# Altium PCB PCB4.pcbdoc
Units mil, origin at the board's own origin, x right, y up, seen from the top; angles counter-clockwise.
Board outline 1996.06 x 3846.46 mil, 2 copper layers (Top Layer, Bottom Layer); 8 components, 12 nets, 57 pads, 0 vias.
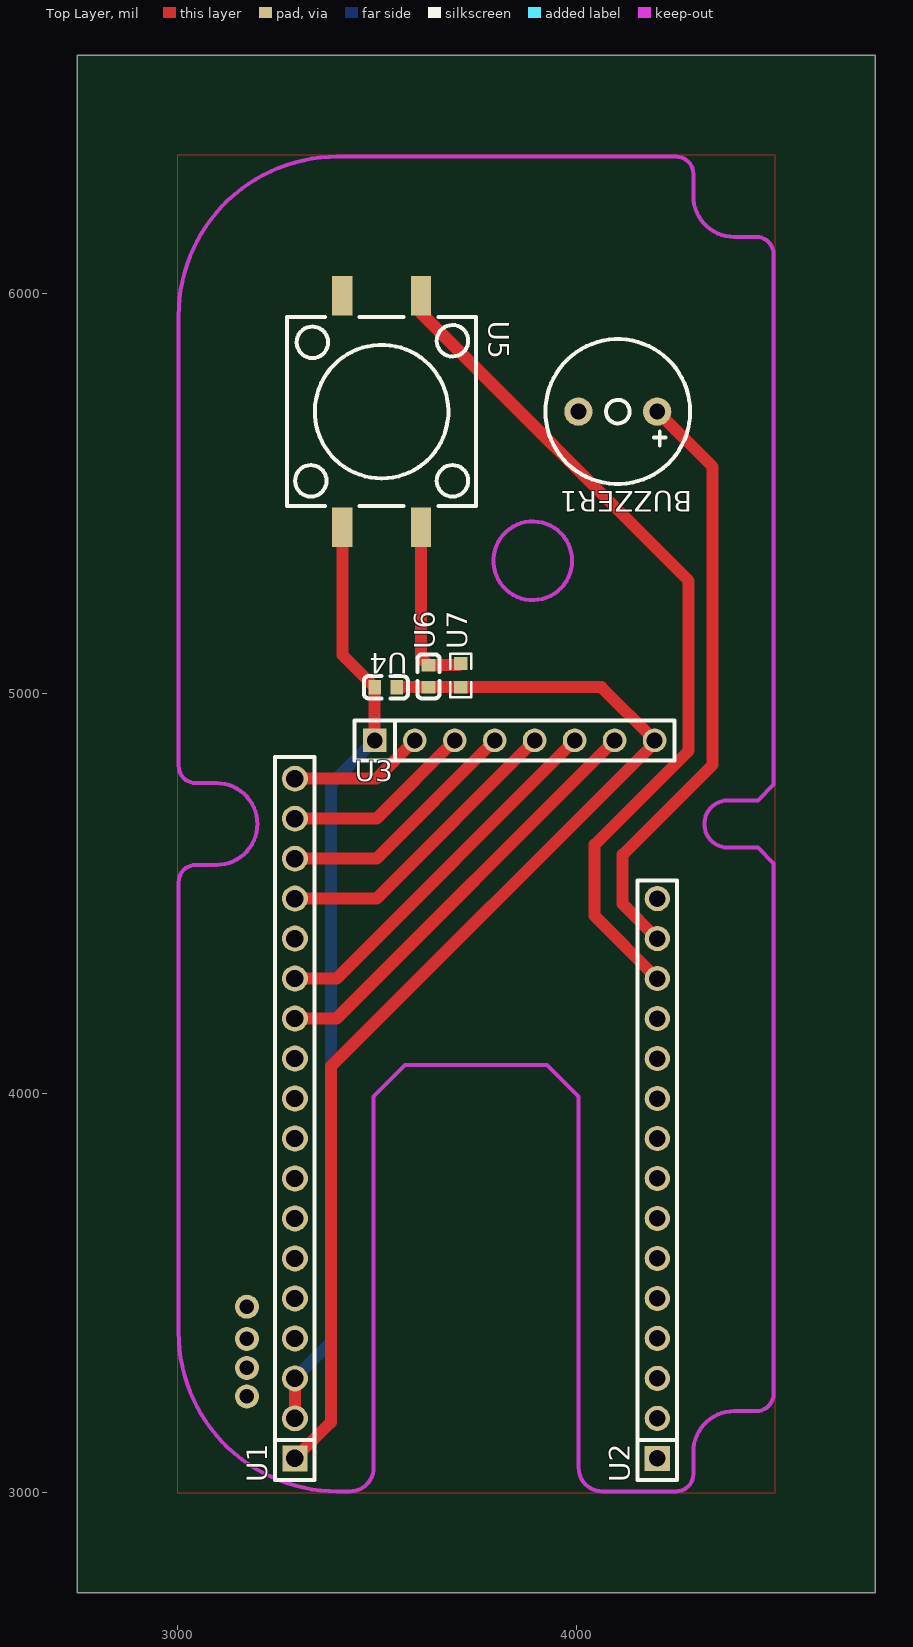
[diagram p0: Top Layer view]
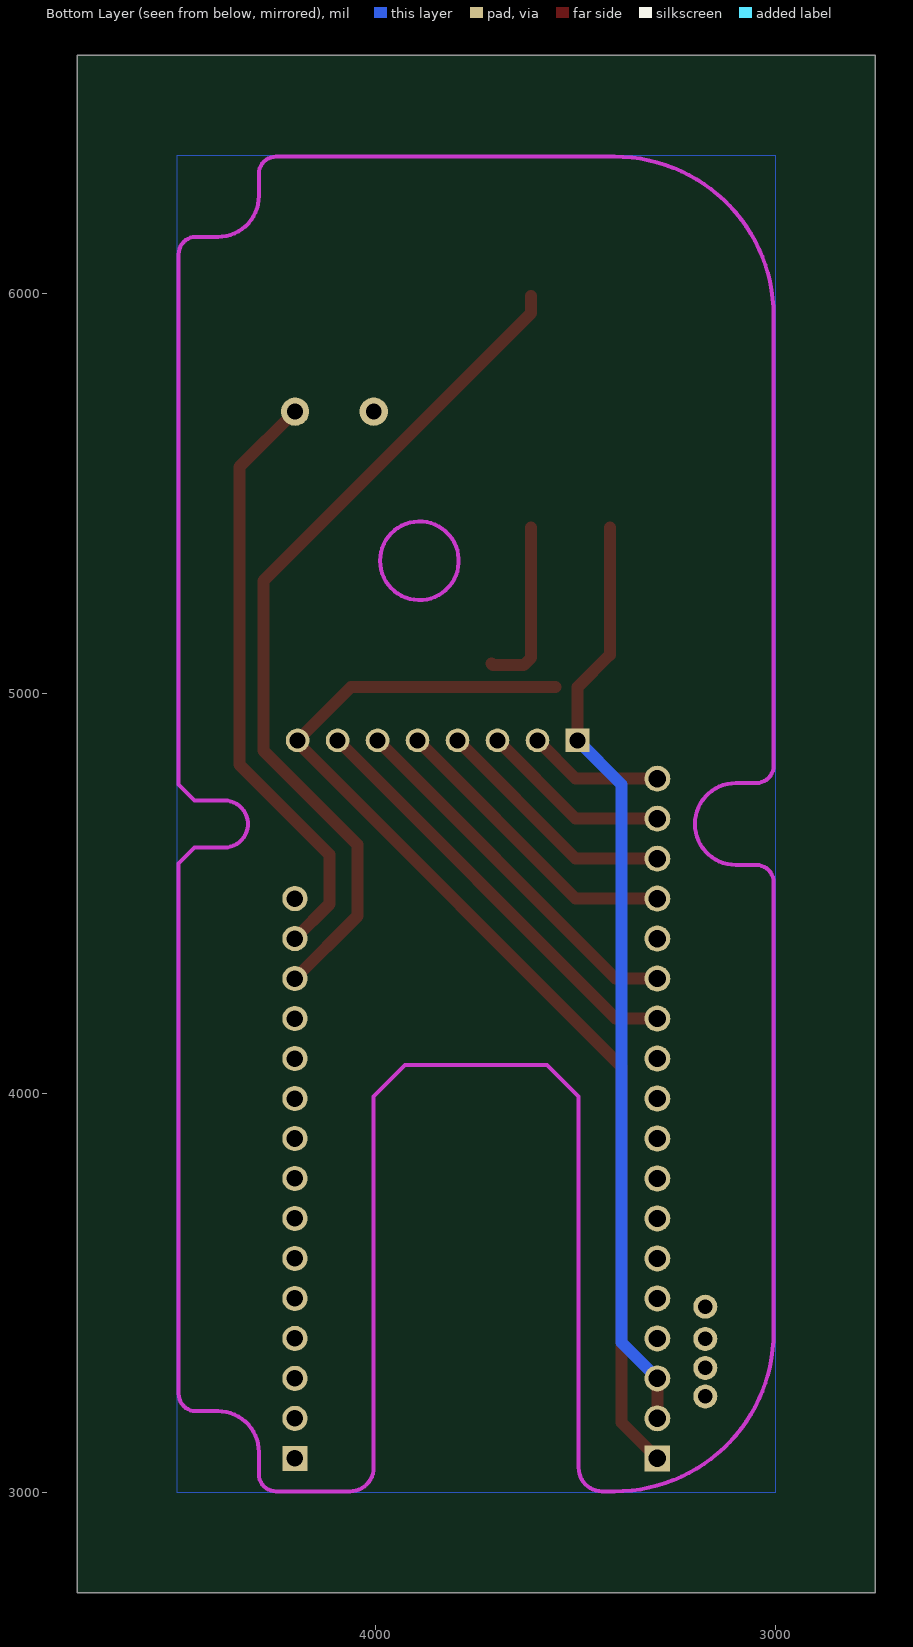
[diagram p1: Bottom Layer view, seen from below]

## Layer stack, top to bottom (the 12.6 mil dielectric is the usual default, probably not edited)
Top Layer: signal copper (thickness not stored)
Dielectric: dielectric 12.6, FR-4, Dk 4.8
Bottom Layer: signal copper (thickness not stored)

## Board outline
4746.06,2750 2750,2750 2750,6596.46 4746.06,6596.46

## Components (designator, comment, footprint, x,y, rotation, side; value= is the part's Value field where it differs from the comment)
BUZZER1 "YS-MBZ9055DYB03" BUZ-TH_BD9.0-P5.00-D0.6-FD 4102.38,5704.72 r180 top
U1 "P125-1118A0BS116A1" HDR-TH_18P-P2.54-V-M 3294.78,3936.61 r90 top
U2 "XDZ254C-1-15-Z-3.0-G1" HDR-TH_15P-P2.54-V-M 4201.28,3786.61 r90 top
U3 "PZ254-1-08-Z-2.5-G1" HDR-TH_8P-P2.54-V-M 3844.51,4882.28 r0 top
U4 "VJ0603Y105KXJCW1BC" C0603 3522.07,5015.27 r180 top
U5 "HX TS127TP 250gf 009" SW-SMD_4P-L12.0-W12.0-P5.00-LS15.4 3511.81,5704.72 r270 top
U6 "VJ0603Y105KXJCW1BC" C0603 3629.08,5042.83 r90 top
U7 "AC0603JR-131KL" R0603 3709.78,5044.93 r90 top

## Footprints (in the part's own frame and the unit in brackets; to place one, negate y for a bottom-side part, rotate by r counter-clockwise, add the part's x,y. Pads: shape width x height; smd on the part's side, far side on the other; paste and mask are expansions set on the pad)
BUZ-TH_BD9.0-P5.00-D0.6-FD [mm]
  round 1.8 hole 1 copper offset 0,0 mask+0.051: 1(-2.5,0)
  round 1.8 hole 1 mask+0.051: 2(2.5,0)
  silkscreen extent -4.6,-4.6 4.6,4.6
C0603 [mm]
  rect 0.8x0.9 smd mask+0.051: 1(-0.7,0) 2(0.7,0)
  silkscreen extent -1.41,-0.71 1.39,0.72
HDR-TH_8P-P2.54-V-M [mm]
  rect 1.5x1.5 hole 1 mask+0.051: 1(-8.89,0)
  round 1.5 hole 1 mask+0.051: 2(-6.35,0) 3(-3.81,0) 4(-1.27,0) 5(1.27,0) 6(3.81,0) 7(6.35,0) 8(8.89,0)
  silkscreen extent -10.16,-1.27 10.16,1.27
HDR-TH_15P-P2.54-V-M [mm]
  rect 1.6x1.6 hole 1.05 paste+0 mask+0.05: 1(-17.78,0)
  round 1.6 hole 1.05 paste+0 mask+0.05: 2(-15.24,0) 3(-12.7,0) 4(-10.16,0) 5(-7.62,0) 6(-5.08,0) 7(-2.54,0) 8(0,0) 9(2.54,0) 10(5.08,0) 11(7.62,0) 12(10.16,0) 13(12.7,0) 14(15.24,0) 15(17.78,0)
  silkscreen extent -19.17,-1.25 18.93,1.25
HDR-TH_18P-P2.54-V-M [mm]
  rect 1.65x1.6 hole 1.1 mask+0.051: 1(-21.59,0)
  round 1.65 hole 1.1 mask+0.051: 2(-19.05,0) 3(-16.51,0) 4(-13.97,0) 5(-11.43,0) 6(-8.89,0) 7(-6.35,0) 8(-3.81,0) 9(-1.27,0) 10(1.27,0) 11(3.81,0) 12(6.35,0) 13(8.89,0) 14(11.43,0) 15(13.97,0) 16(16.51,0) 17(19.05,0) 18(21.59,0)
  silkscreen extent -22.98,-1.25 22.98,1.25
R0603 [mil]
  rect 31.75x34.02 smd paste-3937.01 mask+2: 1(-29.66,0) 2(29.66,0)
  silkscreen extent -55,-26 55,26
SW-SMD_4P-L12.0-W12.0-P5.00-LS15.4 [mm]
  rect 2.5x1.3 smd paste+0 mask+0.05: 1(7.358,-2.5) 2(-7.358,-2.5) 3(7.358,2.5) 4(-7.358,2.5)
  silkscreen extent -6,-6 6,6

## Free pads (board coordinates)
  round 60 hole 36 mask+2: 19(3174.78,3241.61) 20(3174.78,3312.81) 21(3174.78,3385.47) 22(3174.78,3465.91)

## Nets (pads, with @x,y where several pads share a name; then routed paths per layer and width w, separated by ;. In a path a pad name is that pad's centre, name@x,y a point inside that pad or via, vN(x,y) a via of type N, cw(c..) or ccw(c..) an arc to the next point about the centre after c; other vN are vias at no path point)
$1N836: U5.3 U6.2 U7.2 | length 434.9
  Top Layer w30: U5.3 3610.24,5089.23 U6.2 3705.58,5070.39 U7.2
BUTTON: U2.13 U5.4 | length 2147.3
  Top Layer w30: U5.4 3610.24,5951.16 4279.78,5281.61 4279.78,4856.61 4044.78,4621.61 4044.78,4443.11 U2.13
BUZ: BUZZER1.1 U2.14 | length 1505.2
  Top Layer w30: BUZZER1.1 4201.67,5704.72 4339.78,5566.61 4339.78,4821.61 4114.78,4596.61 4114.78,4473.11 U2.14
D: U1.18 U3.2 | length 339.4
  Top Layer w30: U1.18 3498.84,4786.61 U3.2
D1: U1.17 U3.3 | length 480.8
  Top Layer w30: U1.17 3498.84,4686.61 U3.3
D2: U1.16 U3.4 | length 622.2
  Top Layer w30: U1.16 3498.84,4586.61 U3.4
D3: U1.15 U3.5 | length 763.6
  Top Layer w30: U1.15 3498.84,4486.61 U3.5
D4: U1.13 U3.6 | length 946.5
  Top Layer w30: U1.13 3398.84,4286.61 U3.6
D5: U1.12 U3.7 | length 1087.9
  Top Layer w30: U1.12 3398.84,4186.61 U3.7
GND: BUZZER1.2 pad.19 pad.20 pad.21 pad.22 U1.1 U2.1 U3.8 U4.1 U6.1 U7.1 | length 2868.3
  Top Layer w30: U1.1 3384.78,3176.61 3384.78,4066.61 4194.51,4876.34 U3.8 4061.52,5015.27 U7.1 U6.1 U4.1
VCC: U1.2 U1.3 U3.1 U4.2 U5.1 | length 2344.8
  Top Layer w30: U1.2 U1.3 ; U5.1 3413.39,5096.39 U4.2 U3.1
  Bottom Layer w30: U1.3 3384.78,3376.61 3384.78,4772.56 U3.1
"": U1.4 U1.5 U1.6 U1.7 U1.8 U1.9 U1.10 U1.11 U1.14 U2.2 U2.3 U2.4 U2.5 U2.6 U2.7 U2.8 U2.9 U2.10 U2.11 U2.12 U2.15 U5.2

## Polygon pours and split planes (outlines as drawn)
GND on Top Layer (solid, remove dead copper, pour order 0): 3000,3000 4496.06,3000 4496.06,6346.46 3000,6346.46
GND on Bottom Layer (solid, remove dead copper, pour order 1): 3000,3000 4496.06,3000 4496.06,6346.46 3000,6346.46

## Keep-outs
Board Outline Layer:
  circle w10 net "": c3889.78,5331.61 r98.43
  lines w10 net "": 3043.33,4570.87 3098.44,4570.87 ccw(c3098.44,4673.23) 3098.44,4775.59 3043.33,4775.59 ; 3047.22,4570.87 ccw(c3047.22,4527.56) 3003.92,4527.56 3003.92,3401.57 ccw(c3401.56,3401.57) 3401.56,3003.94 3432.58,3003.94 ccw(c3432.58,3062.99) 3491.63,3062.99 3491.63,3992.13 3570.37,4070.87 3925.69,4070.87 4004.43,3992.13 4004.43,3062.99 ccw(c4063.48,3062.99) 4063.48,3003.94 4248.01,3003.94 ccw(c4248.01,3047.24) 4291.32,3047.24 4291.32,3102.36 cw(c4393.68,3102.36) 4393.68,3204.72 4448.8,3204.72 ccw(c4448.8,3248.03) 4492.11,3248.03 4492.11,4574.8 4452.74,4614.17 4377.97,4614.17 cw(c4377.97,4673.23) 4377.97,4732.28 4452.74,4732.28 4492.11,4771.65 4492.11,6098.43 ccw(c4448.8,6098.43) 4448.8,6141.73 4393.68,6141.73 cw(c4393.68,6244.09) 4291.32,6244.09 4291.32,6299.21 ccw(c4248.01,6299.21) 4248.01,6342.52 3401.56,6342.52 ccw(c3401.56,5944.88) 3003.92,5944.88 3003.92,4818.9 ccw(c3047.22,4818.9) 3047.22,4775.59

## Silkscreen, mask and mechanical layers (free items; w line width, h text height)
Mech6:
  lines w10 net "": 3000,3055.12 3000,6314.96 ; 3246.08,3086.61 3294.78,3086.61 4201.28,3086.61 4249.98,3086.61 ; 4094.49,4693.31 4496.06,4693.31 4496.06,3031.89 ; 4496.06,3055.12 4496.06,6346.46 ; 4496.06,4653.94 4496.06,4842.91 ; 3000,3000 4496.06,3000 ; 3000,3000 3000,6346.46 ; 3000,3000 4496.06,3000 ; 3000,3000 3000,6346.46 ; 3000,6346.46 4496.06,6346.46 ; 3000,6346.46 4496.06,6346.46 ; 4496.06,3000 4496.06,6346.46 ; 4496.06,3000 4496.06,6346.46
